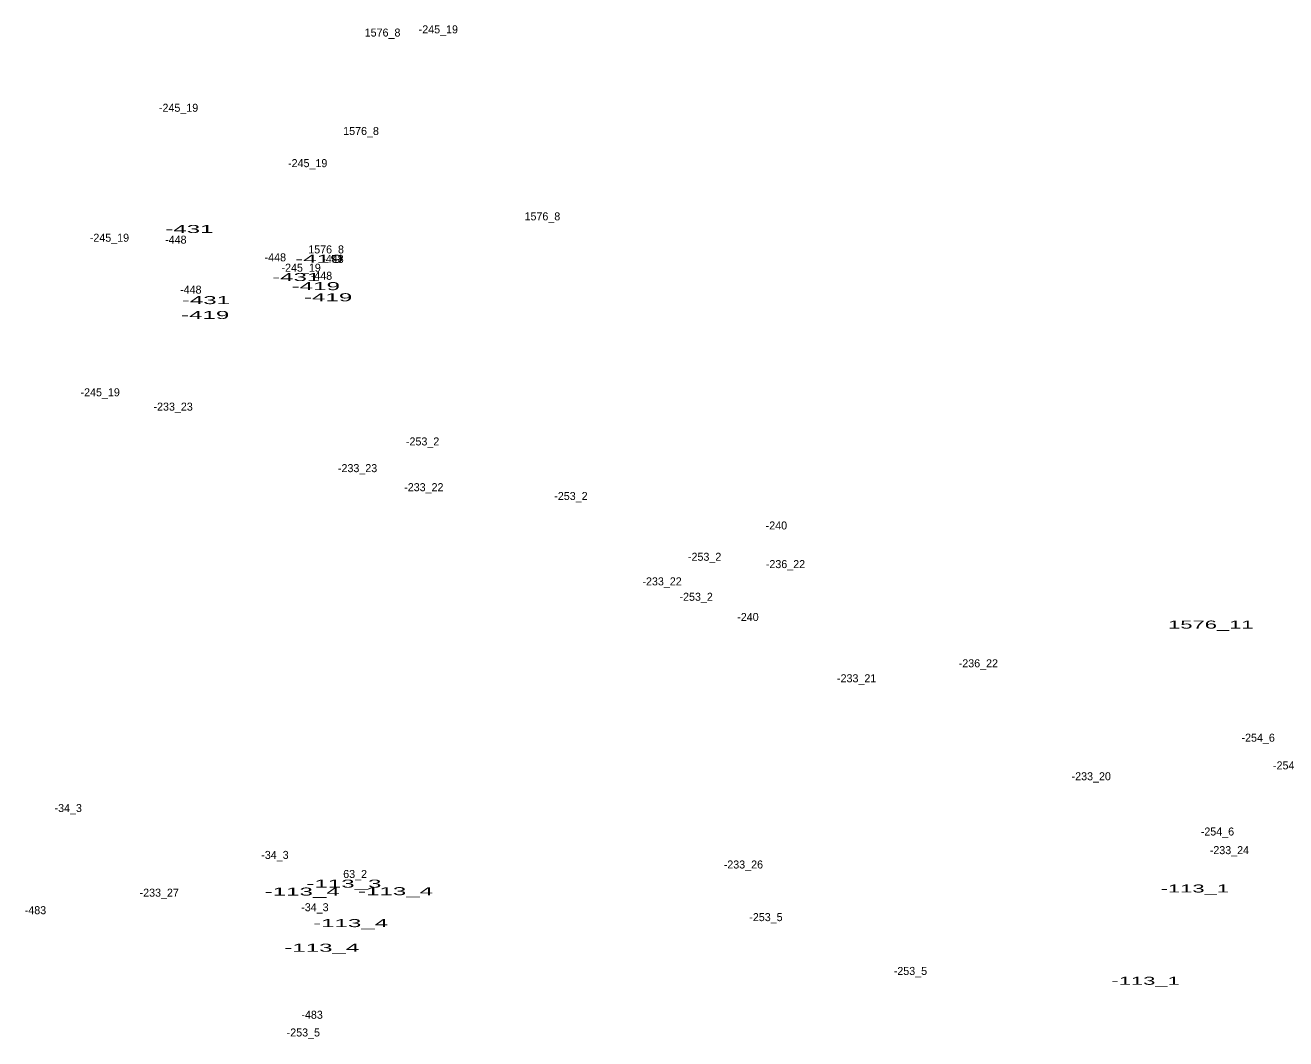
# Model space of a CAD drawing. Extents: x -660434 to -656144, y -997850 to -994016.
# Drawn here: x -660104 to -659474, y -994523 to -994016 of the extents above; entities that cross this region are included whole.
import ezdxf
from ezdxf.enums import TextEntityAlignment as Align

# ---------------------------------------------------------------- set-up
doc = ezdxf.new("R2010")
doc.units = 0
doc.header["$LTSCALE"] = 1.6
doc.layers.add('24', color=7, linetype='Continuous')

msp = doc.modelspace()

# ---------------------------------------------------------------- texts
at = {"layer": '24'}
for s, p in [('-245_19', (-659897.545, -994020.36)), ('1576_8', (-659925.41, -994021.97)), ('-245_19', (-660027.345, -994059.54)), ('1576_8', (-659936.16, -994071.14)), ('-245_19', (-659962.825, -994087.2)), ('1576_8', (-659845.54, -994113.78)), ('-245_19', (-660061.895, -994124.46)), ('-448', (-660028.723, -994125.42)), ('-448', (-659978.993, -994134.25)), ('1576_8', (-659953.63, -994130.3)), ('-245_19', (-659966.095, -994139.44)), ('-448', (-659950.193, -994135.02)), ('-448', (-659955.953, -994143.47)), ('-448', (-660021.233, -994150.39)), ('-245_19', (-660066.515, -994201.68)), ('-233_23', (-660030.061, -994208.83)), ('-253_2', (-659905.402, -994226.22)), ('-233_23', (-659937.901, -994239.56)), ('-233_22', (-659904.781, -994249.07)), ('-253_2', (-659831.282, -994253.49)), ('-240', (-659728.603, -994268.2)), ('-253_2', (-659764.472, -994283.84)), ('-236_22', (-659724.067, -994287.5)), ('-233_22', (-659785.731, -994296.13)), ('-253_2', (-659768.692, -994303.82)), ('-240', (-659742.813, -994313.92)), ('-236_22', (-659627.677, -994337.05)), ('-233_21', (-659688.495, -994344.53)), ('-254_6', (-659487.852, -994374.22)), ('-254_6', (-659472.112, -994388.05)), ('-233_20', (-659571.265, -994393.48)), ('-34_3', (-660082.487, -994409.35)), ('-254_6', (-659508.202, -994421.08)), ('-233_24', (-659502.226, -994430.39)), ('-34_3', (-659979.187, -994432.78)), ('63_2', (-659939.13, -994442.3)), ('-233_26', (-659745.097, -994437.56)), ('-233_27', (-660037.017, -994451.65)), ('-483', (-660098.869, -994460.39)), ('-34_3', (-659959.217, -994458.91)), ('-253_5', (-659733.822, -994463.85)), ('-253_5', (-659661.622, -994490.74)), ('-483', (-659960.619, -994512.63)), ('-253_5', (-659965.002, -994521.47))]:
    msp.add_text(s, height=4, dxfattribs=at).set_placement(p, align=Align.CENTER)
for s, width, p in [('-431', 2.25, (-660021.936, -994120.09)), ('-419', 2.25, (-659957.031, -994135)), ('-431', 2.25, (-659968.556, -994144.1)), ('-419', 2.25, (-659958.751, -994148.64)), ('-431', 2.25, (-660013.676, -994155.62)), ('-419', 2.25, (-659952.611, -994154.2)), ('-419', 2.25, (-660014.051, -994163.04)), ('1576_11', 2.05, (-659511.491, -994317.71)), ('-113_3', 2.25, (-659944.717, -994447.12)), ('-113_1', 2.05, (-659519.514, -994449.55)), ('-113_4', 2.25, (-659965.573, -994451.09)), ('-113_4', 2.25, (-659918.913, -994450.89)), ('-113_4', 2.25, (-659941.383, -994466.84)), ('-113_4', 2.25, (-659955.783, -994479.13)), ('-113_1', 2.05, (-659544.094, -994495.65))]:
    msp.add_text(s, height=4, dxfattribs=dict(at, width=width)).set_placement(p, align=Align.CENTER)

doc.saveas('drawing.dxf')
